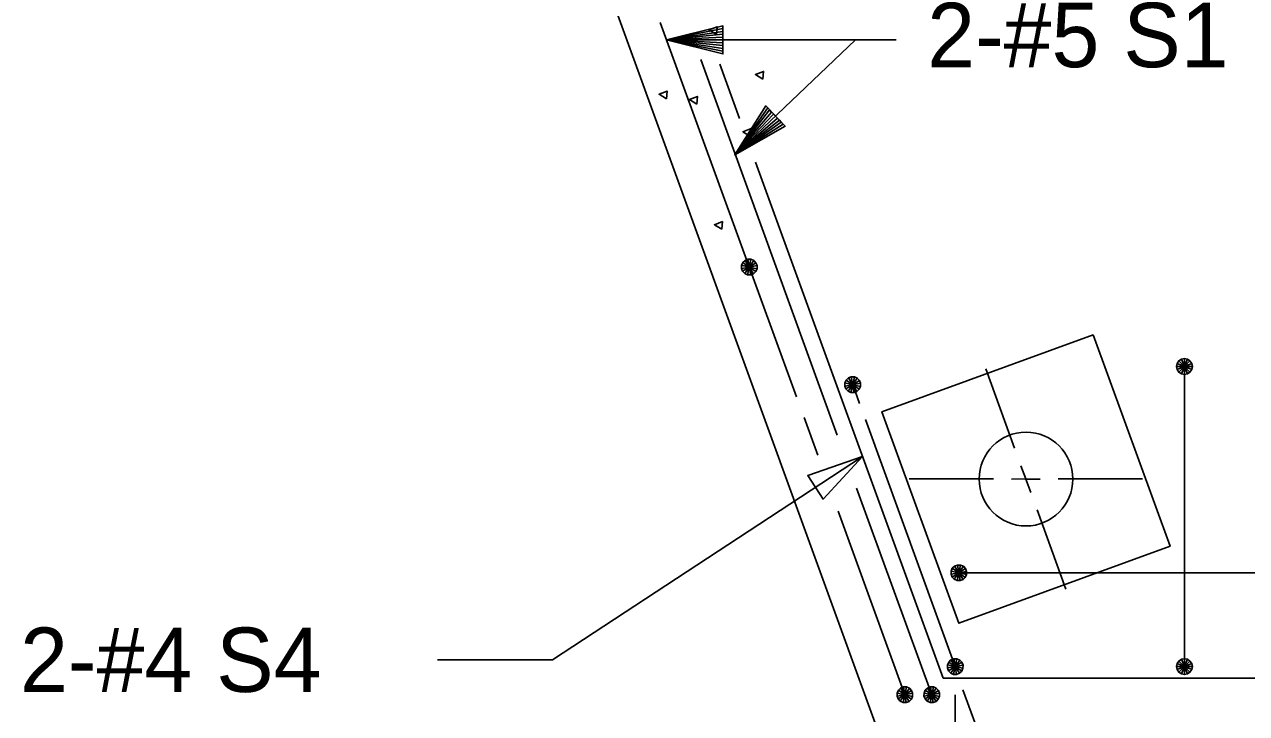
# Model space of a CAD drawing. Extents: x -408 to -23, y -15 to 117.
# Drawn here: x -113.46 to -110.743, y 60.431 to 61.962 of the extents above; entities that cross this region are included whole.
import ezdxf

# ---------------------------------------------------------------- set-up
doc = ezdxf.new("R2010")
doc.units = 0
for name, color, linetype in [('Arrowhead Terminators CELL', 7, 'Continuous'), ('Dimension Lines', 7, 'Continuous'), ('Rebar Lines', 7, 'Continuous'), ('Sup Concrete Girder Lines', 7, 'Continuous'), ('Sup Cored Slab Unit', 7, 'Continuous'), ('Text', 7, 'Continuous')]:
    doc.layers.add(name, color=color, linetype=linetype)

msp = doc.modelspace()

# ---------------------------------------------------------------- linework, layer by layer
at = {"layer": 'Arrowhead Terminators CELL'}
msp.add_lwpolyline([(-111.5972, 61.0023), (-111.7188, 60.9599), (-111.6846, 60.9076)], close=True, dxfattribs=at)
at = {"layer": 'Dimension Lines'}
for p, q in [((-112.0325, 61.9279), (-111.6127, 61.928)), ((-111.2589, 61.021), (-111.3231, 61.1971)), ((-111.3055, 60.9524), (-111.493, 60.9523)), ((-110.9748, 60.9523), (-111.1624, 60.9523)), ((-111.1448, 60.7075), (-111.209, 60.8837)), ((-111.2151, 60.0476), (-111.3738, 60.4839)), ((-111.3909, 59.5616), (-111.3909, 60.4729))]:
    msp.add_line(p, q, dxfattribs=at)
for points in [[(-111.9075, 61.9279), (-111.9075, 61.9216), (-112.0325, 61.9279), (-111.9075, 61.9154), (-111.9075, 61.9091), (-112.0325, 61.9279), (-111.9075, 61.9029), (-111.9075, 61.8966), (-112.0325, 61.9279), (-111.9075, 61.9591), (-111.9075, 61.9529), (-112.0325, 61.9279), (-111.9075, 61.9466), (-111.9075, 61.9404), (-112.0325, 61.9279), (-111.9075, 61.9341), (-111.9075, 61.8966), (-111.9075, 61.9591), (-112.0325, 61.9279), (-111.9075, 61.8966)], [(-111.8812, 61.6725), (-111.6127, 61.928), (-111.5219, 61.928)], [(-111.7906, 61.7587), (-111.7863, 61.7541), (-111.8812, 61.6725), (-111.782, 61.7496), (-111.7777, 61.7451), (-111.8812, 61.6725), (-111.7734, 61.7406), (-111.7691, 61.7361), (-111.8812, 61.6725), (-111.8122, 61.7813), (-111.8078, 61.7768), (-111.8812, 61.6725), (-111.8035, 61.7723), (-111.7992, 61.7677), (-111.8812, 61.6725), (-111.7949, 61.7632), (-111.7691, 61.7361), (-111.8122, 61.7813), (-111.8812, 61.6725), (-111.7691, 61.7361)], [(-112.5423, 60.5506), (-112.2863, 60.5506), (-111.5972, 61.0023)], [(-111.2448, 60.9817), (-111.234, 60.9523), (-111.2655, 60.9522)], [(-111.223, 60.9226), (-111.2337, 60.9521), (-111.2022, 60.9522)]]:
    msp.add_lwpolyline(points, dxfattribs=at)
at = {"layer": 'Rebar Lines'}
for p, q in [((-111.7438, 61.1348), (-112.0467, 61.9669)), ((-111.6531, 61.0499), (-111.9566, 61.884)), ((-111.8706, 61.7536), (-111.9145, 61.8743)), ((-111.4178, 60.5094), (-111.8352, 61.6563)), ((-110.8814, 60.5286), (-110.8814, 61.2021)), ((-111.6037, 61.12), (-111.6189, 61.1619)), ((-111.6966, 61.0051), (-111.7271, 61.089)), ((-111.3909, 60.5354), (-111.5907, 61.0843)), ((-111.4432, 60.4729), (-111.6102, 60.9321)), ((-111.5029, 60.4729), (-111.6512, 60.8804)), ((-111.3829, 60.7438), (-108.6954, 60.7438)), ((-110.0604, 60.5094), (-111.4178, 60.5094))]:
    msp.add_line(p, q, dxfattribs=at)
for points in [[(-111.8661, 61.4201), (-111.866, 61.427), (-111.8633, 61.4333), (-111.8583, 61.4381), (-111.8519, 61.4406), (-111.845, 61.4405), (-111.8387, 61.4376), (-111.8339, 61.4327), (-111.8314, 61.4263), (-111.8316, 61.4194), (-111.8344, 61.4131), (-111.8393, 61.4083), (-111.8457, 61.4058), (-111.8526, 61.406), (-111.8589, 61.4087), (-111.8637, 61.4137), (-111.8661, 61.4201), (-111.8488, 61.4232), (-111.8314, 61.4263), (-111.8339, 61.4327), (-111.8488, 61.4232), (-111.8387, 61.4376), (-111.845, 61.4405), (-111.8488, 61.4232), (-111.8519, 61.4406), (-111.8583, 61.4381), (-111.8488, 61.4232), (-111.8633, 61.4333), (-111.866, 61.427), (-111.8488, 61.4232), (-111.8637, 61.4137), (-111.8589, 61.4087), (-111.8488, 61.4232), (-111.8526, 61.406), (-111.8457, 61.4058), (-111.8488, 61.4232), (-111.8393, 61.4083), (-111.8344, 61.4131), (-111.8488, 61.4232), (-111.8316, 61.4194)], [(-110.899, 61.2021), (-110.8977, 61.2088), (-110.8939, 61.2145), (-110.8882, 61.2184), (-110.8814, 61.2197), (-110.8747, 61.2184), (-110.869, 61.2145), (-110.8652, 61.2088), (-110.8638, 61.2021), (-110.8652, 61.1953), (-110.869, 61.1896), (-110.8747, 61.1858), (-110.8814, 61.1844), (-110.8882, 61.1858), (-110.8939, 61.1896), (-110.8977, 61.1953), (-110.899, 61.2021), (-110.8814, 61.2021), (-110.8638, 61.2021), (-110.8652, 61.2088), (-110.8814, 61.2021), (-110.869, 61.2145), (-110.8747, 61.2184), (-110.8814, 61.2021), (-110.8814, 61.2197), (-110.8882, 61.2184), (-110.8814, 61.2021), (-110.8939, 61.2145), (-110.8977, 61.2088), (-110.8814, 61.2021), (-110.8977, 61.1953), (-110.8939, 61.1896), (-110.8814, 61.2021), (-110.8882, 61.1858), (-110.8814, 61.1844), (-110.8814, 61.2021), (-110.8747, 61.1858), (-110.869, 61.1896), (-110.8814, 61.2021), (-110.8652, 61.1953)], [(-111.6363, 61.1588), (-111.6362, 61.1656), (-111.6334, 61.1719), (-111.6285, 61.1767), (-111.622, 61.1792), (-111.6151, 61.1791), (-111.6088, 61.1763), (-111.6041, 61.1714), (-111.6016, 61.1649), (-111.6017, 61.1581), (-111.6045, 61.1518), (-111.6094, 61.147), (-111.6158, 61.1445), (-111.6228, 61.1446), (-111.629, 61.1474), (-111.6338, 61.1524), (-111.6363, 61.1588), (-111.6189, 61.1618), (-111.6016, 61.1649), (-111.6041, 61.1714), (-111.6189, 61.1618), (-111.6088, 61.1763), (-111.6151, 61.1791), (-111.6189, 61.1618), (-111.622, 61.1792), (-111.6285, 61.1767), (-111.6189, 61.1618), (-111.6334, 61.1719), (-111.6362, 61.1656), (-111.6189, 61.1618), (-111.6338, 61.1524), (-111.629, 61.1474), (-111.6189, 61.1618), (-111.6228, 61.1446), (-111.6158, 61.1445), (-111.6189, 61.1618), (-111.6094, 61.147), (-111.6045, 61.1518), (-111.6189, 61.1618), (-111.6017, 61.1581)], [(-111.4002, 60.7407), (-111.4001, 60.7476), (-111.3974, 60.7539), (-111.3924, 60.7587), (-111.386, 60.7611), (-111.3791, 60.761), (-111.3728, 60.7582), (-111.3681, 60.7533), (-111.3656, 60.7469), (-111.3658, 60.74), (-111.3685, 60.7337), (-111.3734, 60.7289), (-111.3799, 60.7264), (-111.3867, 60.7265), (-111.393, 60.7293), (-111.3978, 60.7343), (-111.4002, 60.7407), (-111.3829, 60.7438), (-111.3656, 60.7469), (-111.3681, 60.7533), (-111.3829, 60.7438), (-111.3728, 60.7582), (-111.3791, 60.761), (-111.3829, 60.7438), (-111.386, 60.7611), (-111.3924, 60.7587), (-111.3829, 60.7438), (-111.3974, 60.7539), (-111.4001, 60.7476), (-111.3829, 60.7438), (-111.3978, 60.7343), (-111.393, 60.7293), (-111.3829, 60.7438), (-111.3867, 60.7265), (-111.3799, 60.7264), (-111.3829, 60.7438), (-111.3734, 60.7289), (-111.3685, 60.7337), (-111.3829, 60.7438), (-111.3658, 60.74)], [(-111.4083, 60.5323), (-111.4082, 60.5392), (-111.4054, 60.5455), (-111.4004, 60.5503), (-111.394, 60.5527), (-111.3872, 60.5526), (-111.3808, 60.5498), (-111.3761, 60.5449), (-111.3736, 60.5385), (-111.3738, 60.5316), (-111.3765, 60.5253), (-111.3814, 60.5205), (-111.3878, 60.518), (-111.3948, 60.5182), (-111.401, 60.5209), (-111.4058, 60.5259), (-111.4083, 60.5323), (-111.3909, 60.5354), (-111.3736, 60.5385), (-111.3761, 60.5449), (-111.3909, 60.5354), (-111.3808, 60.5498), (-111.3872, 60.5526), (-111.3909, 60.5354), (-111.394, 60.5527), (-111.4004, 60.5503), (-111.3909, 60.5354), (-111.4054, 60.5455), (-111.4082, 60.5392), (-111.3909, 60.5354), (-111.4058, 60.5259), (-111.401, 60.5209), (-111.3909, 60.5354), (-111.3948, 60.5182), (-111.3878, 60.518), (-111.3909, 60.5354), (-111.3814, 60.5205), (-111.3765, 60.5253), (-111.3909, 60.5354), (-111.3738, 60.5316)], [(-110.899, 60.5354), (-110.8977, 60.5421), (-110.8939, 60.5478), (-110.8882, 60.5517), (-110.8814, 60.553), (-110.8747, 60.5517), (-110.869, 60.5478), (-110.8652, 60.5422), (-110.8638, 60.5354), (-110.8652, 60.5287), (-110.869, 60.523), (-110.8747, 60.5191), (-110.8814, 60.5177), (-110.8882, 60.5191), (-110.8939, 60.5229), (-110.8977, 60.5286), (-110.899, 60.5354), (-110.8814, 60.5354), (-110.8638, 60.5354), (-110.8652, 60.5422), (-110.8814, 60.5354), (-110.869, 60.5478), (-110.8747, 60.5517), (-110.8814, 60.5354), (-110.8814, 60.553), (-110.8882, 60.5517), (-110.8814, 60.5354), (-110.8939, 60.5478), (-110.8977, 60.5421), (-110.8814, 60.5354), (-110.8977, 60.5286), (-110.8939, 60.5229), (-110.8814, 60.5354), (-110.8882, 60.5191), (-110.8814, 60.5177), (-110.8814, 60.5354), (-110.8747, 60.5191), (-110.869, 60.523), (-110.8814, 60.5354), (-110.8652, 60.5287)], [(-111.5202, 60.4698), (-111.5201, 60.4767), (-111.5174, 60.483), (-111.5124, 60.4878), (-111.506, 60.4902), (-111.4991, 60.4901), (-111.4928, 60.4873), (-111.4881, 60.4824), (-111.4856, 60.476), (-111.4858, 60.4691), (-111.4885, 60.4628), (-111.4934, 60.458), (-111.4999, 60.4555), (-111.5067, 60.4557), (-111.513, 60.4584), (-111.5178, 60.4634), (-111.5202, 60.4698), (-111.5029, 60.4729), (-111.4856, 60.476), (-111.4881, 60.4824), (-111.5029, 60.4729), (-111.4928, 60.4873), (-111.4991, 60.4901), (-111.5029, 60.4729), (-111.506, 60.4902), (-111.5124, 60.4878), (-111.5029, 60.4729), (-111.5174, 60.483), (-111.5201, 60.4767), (-111.5029, 60.4729), (-111.5178, 60.4634), (-111.513, 60.4584), (-111.5029, 60.4729), (-111.5067, 60.4557), (-111.4999, 60.4555), (-111.5029, 60.4729), (-111.4934, 60.458), (-111.4885, 60.4628), (-111.5029, 60.4729), (-111.4858, 60.4691)], [(-111.4605, 60.4699), (-111.4603, 60.4767), (-111.4576, 60.483), (-111.4526, 60.4878), (-111.4462, 60.4902), (-111.4394, 60.4901), (-111.4331, 60.4873), (-111.4283, 60.4824), (-111.4258, 60.476), (-111.426, 60.4691), (-111.4287, 60.4628), (-111.4336, 60.4581), (-111.4401, 60.4556), (-111.447, 60.4557), (-111.4532, 60.4585), (-111.458, 60.4634), (-111.4605, 60.4699), (-111.4432, 60.4729), (-111.4258, 60.476), (-111.4283, 60.4824), (-111.4432, 60.4729), (-111.4331, 60.4873), (-111.4394, 60.4901), (-111.4432, 60.4729), (-111.4462, 60.4902), (-111.4526, 60.4878), (-111.4432, 60.4729), (-111.4576, 60.483), (-111.4603, 60.4767), (-111.4432, 60.4729), (-111.458, 60.4634), (-111.4532, 60.4585), (-111.4432, 60.4729), (-111.447, 60.4557), (-111.4401, 60.4556), (-111.4432, 60.4729), (-111.4336, 60.4581), (-111.4287, 60.4628), (-111.4432, 60.4729), (-111.426, 60.4691)]]:
    msp.add_lwpolyline(points, dxfattribs=at)
at = {"layer": 'Sup Concrete Girder Lines'}
msp.add_line((-111.5081, 60.2438), (-112.5787, 63.185), dxfattribs=at)
for points in [[(-111.9217, 61.94), (-111.9203, 61.9573), (-111.9383, 61.9501), (-111.9217, 61.94)], [(-111.8185, 61.8407), (-111.817, 61.858), (-111.835, 61.8508), (-111.8185, 61.8407)], [(-112.033, 61.797), (-112.0315, 61.8143), (-112.0495, 61.8071), (-112.033, 61.797)], [(-111.9654, 61.7851), (-111.964, 61.8023), (-111.982, 61.7952), (-111.9654, 61.7851)], [(-111.8463, 61.7136), (-111.8448, 61.7308), (-111.8628, 61.7237), (-111.8463, 61.7136)], [(-111.9098, 61.507), (-111.9084, 61.5242), (-111.9263, 61.5171), (-111.9098, 61.507)]]:
    msp.add_lwpolyline(points, dxfattribs=at)
msp.add_circle((-111.2336, 60.9521), 0.1042, dxfattribs=at)
at = {"layer": 'Sup Cored Slab Unit'}
msp.add_lwpolyline([(-111.0842, 61.2725), (-111.5541, 61.1015), (-111.3831, 60.6317), (-110.9132, 60.8027)], close=True, dxfattribs=at)

# ---------------------------------------------------------------- texts
at = {"layer": 'Text'}
for s, p in [('2-#5 S1', (-111.4532, 61.8673)), ('2-#4 S4', (-113.4699, 60.4791))]:
    msp.add_text(s, height=0.14302, dxfattribs=at).set_placement(p)

doc.saveas('drawing.dxf')
